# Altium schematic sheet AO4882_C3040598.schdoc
size 127 x 101 mm
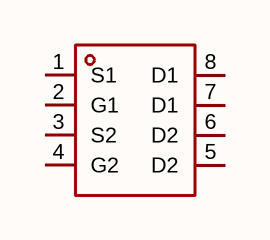
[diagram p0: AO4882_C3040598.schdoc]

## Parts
Q?  ao4882  [SOIC-8_L4.9-W3.9-P1.27-LS6.0-BL]  (value not drawn)

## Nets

Not connected (* = marked no-connect by the designer): Q? 1(S1) 2(G1) 3(S2) 4(G2) 5(D2) 6(D2) 7(D1) 8(D1)

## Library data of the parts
Q? = ao4882: 类型:2个N沟道;漏源电压(Vdss):40V;连续漏极电流(Id):8A;导通电阻(RDS(on)@Vgs,Id):25mΩ@4.5V,4A;功率:2W;阈值电压(Vgs(th)@Id):2.5V@250uA;; Manufacturer: TECH PUBLIC(台舟); Symbol: AO4882_C3040598; AddInBom: yes; ModelId: e81d2f7d937b4a6ab1dca543ff5d56a4; ModelName: SOIC-8_L4.9-W3.9-H1.7-LS6.0-P1.27; ModelTransform: 192.913,236.22,0,0,0,0,0,0,0; Type: 2个N沟道; Drain Source Voltage (Vdss): 40V; Continuous Drain Current (Id): 8A; Power Dissipation (Pd): 2W; Total Gate Charge (Qg@Vgs): 21.6nC@10V; Input Capacitance (Ciss@Vds): 1.45nF@25V; Reverse Transfer Capacitance (Crss@Vds): 220pF@25V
